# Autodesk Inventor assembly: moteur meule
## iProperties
Shininess: 64.0
Length Units: 11269
Angle Units: 11279
Time Units: 11290
Mass Units: 11283
Length Display Precision: 3
Angle Display Precision: 2
Compacted: True
Created: 2005-01
Part Number: moteur meule
Document SubType Name: Assembly
Designer: LEGERET Philippe
Density: 0.0
Volumn: 0.0
Area: 0.0
PropertySet Name: Model Information
Control State: 0
Master: False
Checked Out: False
Author: LEGERET Philippe
